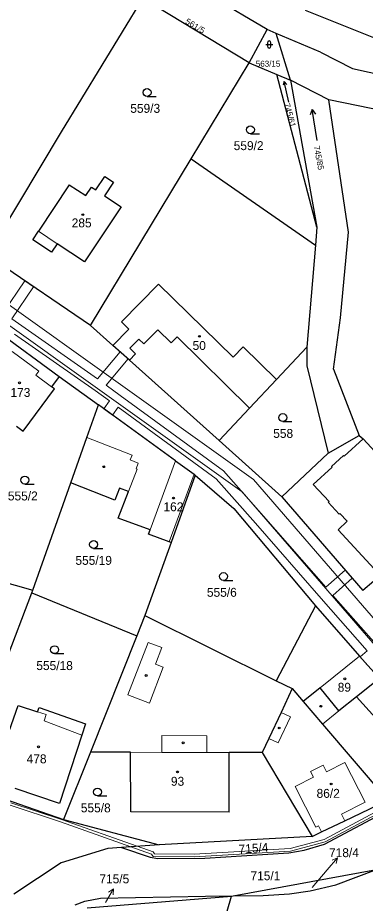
# Model space of a CAD drawing. Extents: x -701211 to -698780, y -1014269 to -1012378.
# Drawn here: x -700367.7 to -700301.5, y -1013402.8 to -1013234 of the extents above; entities that cross this region are included whole.
import ezdxf
from ezdxf.enums import TextEntityAlignment as Align

# ---------------------------------------------------------------- set-up
doc = ezdxf.new("R2010")
doc.units = 0
doc.header["$LTSCALE"] = 0.68
for name, color, linetype, lineweight in [('1', 7, 'Continuous', 25), ('13', 7, 'Continuous', 13), ('3', 7, 'Continuous', 25), ('4', 7, 'Continuous', 13), ('5', 7, 'Continuous', 25), ('7', 7, 'Continuous', 13)]:
    doc.layers.add(name, color=color, linetype=linetype, lineweight=lineweight)
doc.layers.add('2', color=7, linetype='Continuous')

msp = doc.modelspace()

# ---------------------------------------------------------------- linework, layer by layer
at = {"layer": '1'}
for p, q in [((-700320.2, -1013236.27), (-700340.25, -1013224.35)), ((-700359.38, -1013255.74), (-700343.9, -1013230.25)), ((-700323.64, -1013242.58), (-700343.9, -1013230.25)), ((-700312.97, -1013232.56), (-700298.98, -1013238.16)), ((-700323.64, -1013242.58), (-700320.2, -1013236.27)), ((-700318.49, -1013237), (-700320.2, -1013236.27)), ((-700310.08, -1013240.6), (-700318.49, -1013237)), ((-700310.08, -1013240.6), (-700303.94, -1013243.67)), ((-700334.69, -1013260.9), (-700323.64, -1013242.58)), ((-700323.64, -1013242.58), (-700318.37, -1013244.83)), ((-700303.94, -1013243.67), (-700289.22, -1013247.02)), ((-700310.73, -1013273.92), (-700318.37, -1013244.83)), ((-700318.37, -1013244.83), (-700315.79, -1013245.93)), ((-700315.79, -1013245.93), (-700310.73, -1013273.92)), ((-700288.68, -1013253.7), (-700308.46, -1013249.64)), ((-700304.74, -1013274.86), (-700308.46, -1013249.64)), ((-700373.52, -1013279.35), (-700359.38, -1013255.74)), ((-700353.86, -1013292.67), (-700334.69, -1013260.9)), ((-700334.69, -1013260.9), (-700311.02, -1013277.36)), ((-700352.87, -1013266.84), (-700351.16, -1013264.26)), ((-700351.16, -1013264.26), (-700349.49, -1013265.36)), ((-700357.91, -1013265.85), (-700363.78, -1013274.73)), ((-700357.91, -1013265.85), (-700354.78, -1013267.92)), ((-700354.78, -1013267.92), (-700353.71, -1013266.29)), ((-700353.71, -1013266.29), (-700352.87, -1013266.84)), ((-700349.49, -1013265.36), (-700351.2, -1013267.94)), ((-700351.2, -1013267.94), (-700348.01, -1013270.05)), ((-700348.01, -1013270.05), (-700355.04, -1013280.57)), ((-700364.86, -1013276.35), (-700363.78, -1013274.73)), ((-700310.73, -1013273.92), (-700311.02, -1013277.36)), ((-700306.25, -1013291.23), (-700304.74, -1013274.86)), ((-700361.33, -1013278.71), (-700364.86, -1013276.35)), ((-700360.25, -1013277.09), (-700361.33, -1013278.71)), ((-700355.04, -1013280.57), (-700360.25, -1013277.09)), ((-700311.02, -1013277.36), (-700312.68, -1013296.79)), ((-700353.86, -1013292.67), (-700373.52, -1013279.35)), ((-700307.57, -1013300.99), (-700306.25, -1013291.23)), ((-700373.75, -1013292.22), (-700359.82, -1013302.39)), ((-700349.61, -1013296.47), (-700353.86, -1013292.67)), ((-700346.46, -1013299.29), (-700349.61, -1013296.47)), ((-700312.68, -1013296.79), (-700318.45, -1013302.95)), ((-700312.68, -1013296.79), (-700312.67, -1013300.36)), ((-700329.36, -1013314.6), (-700346.46, -1013299.29)), ((-700312.67, -1013300.36), (-700308.61, -1013317.04)), ((-700307.57, -1013300.99), (-700302.67, -1013313.63)), ((-700359.82, -1013302.39), (-700361.27, -1013304.37)), ((-700359.82, -1013302.39), (-700352.35, -1013307.84)), ((-700318.45, -1013302.95), (-700323.58, -1013308.43)), ((-700366.69, -1013312.84), (-700360.75, -1013304.75)), ((-700360.75, -1013304.75), (-700361.27, -1013304.37)), ((-700354.54, -1013314.02), (-700352.35, -1013307.84)), ((-700337.69, -1013318.48), (-700352.35, -1013307.84)), ((-700323.58, -1013308.43), (-700329.36, -1013314.6)), ((-700367.98, -1013311.89), (-700366.69, -1013312.84)), ((-700308.61, -1013317.04), (-700302.67, -1013313.63)), ((-700302.67, -1013313.63), (-700301.95, -1013314.29)), ((-700357.61, -1013322.7), (-700354.54, -1013314.02)), ((-700317.43, -1013325.38), (-700329.36, -1013314.6)), ((-700301.95, -1013314.29), (-700298.93, -1013317.54)), ((-700308.61, -1013317.04), (-700317.43, -1013325.38)), ((-700337.69, -1013318.48), (-700334.15, -1013321.05)), ((-700333.92, -1013321.25), (-700338.52, -1013334.05)), ((-700334.15, -1013321.05), (-700333.92, -1013321.25)), ((-700333.92, -1013321.25), (-700326.57, -1013327.6)), ((-700364.85, -1013343.16), (-700357.61, -1013322.7)), ((-700349.24, -1013325.97), (-700357.61, -1013322.7)), ((-700348.36, -1013323.68), (-700349.24, -1013325.97)), ((-700346.63, -1013324.34), (-700348.36, -1013323.68)), ((-700348.57, -1013329.39), (-700346.63, -1013324.34)), ((-700317.43, -1013325.38), (-700301.97, -1013343.21)), ((-700326.57, -1013327.6), (-700311.03, -1013346.12)), ((-700342.53, -1013331.62), (-700348.57, -1013329.39)), ((-700342.84, -1013332.46), (-700342.53, -1013331.62)), ((-700338.52, -1013334.05), (-700343.52, -1013347.99)), ((-700338.9, -1013333.91), (-700342.84, -1013332.46)), ((-700338.52, -1013334.05), (-700338.9, -1013333.91)), ((-700388.79, -1013336.44), (-700364.85, -1013343.16)), ((-700299.89, -1013341.43), (-700301.97, -1013343.21)), ((-700370.05, -1013356.84), (-700365.02, -1013343.65)), ((-700365.02, -1013343.65), (-700364.85, -1013343.16)), ((-700365.02, -1013343.65), (-700345.07, -1013351.88)), ((-700311.03, -1013346.12), (-700318.51, -1013360.46)), ((-700311.03, -1013346.12), (-700302.61, -1013355.72)), ((-700343.52, -1013347.99), (-700345.07, -1013351.88)), ((-700343.52, -1013347.99), (-700318.51, -1013360.46)), ((-700345.07, -1013351.88), (-700353.89, -1013374.04)), ((-700302.61, -1013355.72), (-700298.84, -1013359.96)), ((-700318.51, -1013360.46), (-700315.45, -1013361.91)), ((-700298.84, -1013359.96), (-700303.19, -1013363.48)), ((-700315.45, -1013361.91), (-700317.57, -1013366.44)), ((-700315.45, -1013361.91), (-700313.33, -1013364.39)), ((-700310.1, -1013361.77), (-700313.33, -1013364.39)), ((-700306.53, -1013366.18), (-700310.1, -1013361.77)), ((-700313.33, -1013364.39), (-700309.65, -1013368.7)), ((-700303.19, -1013363.48), (-700306.53, -1013366.18)), ((-700372.21, -1013378.05), (-700367.64, -1013365.14)), ((-700367.64, -1013365.14), (-700363.99, -1013366.32)), ((-700363.99, -1013366.32), (-700363.67, -1013365.52)), ((-700363.67, -1013365.52), (-700354.85, -1013368.61)), ((-700317.57, -1013366.44), (-700319.9, -1013371.4)), ((-700354.85, -1013368.61), (-700355.55, -1013370.8)), ((-700309.65, -1013368.7), (-700297.27, -1013383.2)), ((-700355.55, -1013370.8), (-700359.78, -1013383.8)), ((-700319.9, -1013371.4), (-700321.18, -1013374.12)), ((-700353.89, -1013374.04), (-700359, -1013386.88)), ((-700346.24, -1013374.05), (-700353.89, -1013374.04)), ((-700346.19, -1013385.41), (-700346.24, -1013374.05)), ((-700327.42, -1013385.46), (-700327.47, -1013374.1)), ((-700321.18, -1013374.12), (-700327.47, -1013374.1)), ((-700321.18, -1013374.12), (-700311.61, -1013390.1)), ((-700378.88, -1013380), (-700359, -1013386.88)), ((-700359.78, -1013383.8), (-700368.23, -1013380.97)), ((-700309.31, -1013391.58), (-700293.7, -1013383.22)), ((-700305.41, -1013387.12), (-700297.27, -1013383.2)), ((-700327.42, -1013385.46), (-700346.19, -1013385.41)), ((-700359, -1013386.88), (-700340.79, -1013391.69)), ((-700309.83, -1013389.24), (-700305.41, -1013387.12)), ((-700311.61, -1013390.1), (-700309.83, -1013389.24)), ((-700311.61, -1013390.1), (-700340.79, -1013391.69)), ((-700350.58, -1013392.37), (-700359.49, -1013395.11)), ((-700347.99, -1013392.19), (-700350.58, -1013392.37)), ((-700340.79, -1013391.69), (-700347.99, -1013392.19)), ((-700347.99, -1013392.19), (-700342.52, -1013394.08)), ((-700316.07, -1013393.23), (-700313.15, -1013392.71)), ((-700313.15, -1013392.71), (-700309.31, -1013391.58)), ((-700342.52, -1013394.08), (-700341.04, -1013394.33)), ((-700341.04, -1013394.33), (-700332.06, -1013394.22)), ((-700332.06, -1013394.22), (-700316.07, -1013393.23)), ((-700359.49, -1013395.11), (-700368.46, -1013401.1)), ((-700326.66, -1013401.42), (-700299.4, -1013396.43)), ((-700307.14, -1013399.33), (-700299.4, -1013396.43)), ((-700311.99, -1013400.47), (-700307.14, -1013399.33)), ((-700354.53, -1013403.68), (-700327.02, -1013401.49)), ((-700351.96, -1013401.87), (-700331.97, -1013401.5)), ((-700331.97, -1013401.5), (-700326.66, -1013401.42)), ((-700328.91, -1013408.1), (-700327.02, -1013401.49)), ((-700327.02, -1013401.49), (-700326.66, -1013401.42)), ((-700326.66, -1013401.42), (-700320.96, -1013401.34)), ((-700320.96, -1013401.34), (-700315.97, -1013401.01)), ((-700315.97, -1013401.01), (-700311.99, -1013400.47)), ((-700356.82, -1013403.15), (-700354.92, -1013402.44)), ((-700354.92, -1013402.44), (-700351.96, -1013401.87))]:
    msp.add_line(p, q, dxfattribs=at)
msp.add_lwpolyline([(-700308.46, -1013249.64), (-700315.79, -1013245.93), (-700318.49, -1013237)], dxfattribs=at)
at = {"layer": '13'}
for points in [[(-700287.36, -1013363.02), (-700322.83, -1013322.02), (-700397.37, -1013268.79), (-700422.31, -1013253.72), (-700469.35, -1013225.78), (-700474.13, -1013223.15), (-700505.21, -1013205.06), (-700510.59, -1013202.27), (-700527.33, -1013194.88), (-700555.49, -1013183.11), (-700559.92, -1013181.38), (-700563.23, -1013179.64), (-700564.89, -1013177.43), (-700602.93, -1013162.92), (-700645.95, -1013152.22), (-700656.81, -1013151.49), (-700669.27, -1013150.25), (-700710.28, -1013153.93)], [(-700710.03, -1013157.08), (-700669.29, -1013153.42), (-700657.08, -1013154.63), (-700646.44, -1013155.36), (-700603.88, -1013165.94), (-700566.87, -1013180.06), (-700565.33, -1013182.09), (-700561.6, -1013184.11), (-700556.67, -1013186.04), (-700528.57, -1013197.79), (-700511.95, -1013205.13), (-700506.73, -1013207.83), (-700475.69, -1013225.9), (-700470.91, -1013228.52), (-700423.94, -1013256.43), (-700399.11, -1013271.43), (-700324.98, -1013324.37), (-700289.83, -1013365.01)], [(-700298.96, -1013354.08), (-700307.69, -1013344.13), (-700303.99, -1013340.88), (-700305.32, -1013339.34), (-700309.03, -1013342.6), (-700320.9, -1013329.04), (-700328.52, -1013320.38), (-700348.23, -1013306), (-700350.86, -1013304.05), (-700346.7, -1013299.07), (-700348.22, -1013297.72), (-700352.51, -1013302.86), (-700368.88, -1013291.43), (-700364.71, -1013285.32), (-700366.39, -1013284.18), (-700370.54, -1013290.25)], [(-700368.32, -1013294.34), (-700352.95, -1013305.07), (-700350.27, -1013307.06), (-700351.35, -1013308.56), (-700349.71, -1013309.76), (-700348.63, -1013308.27), (-700329.92, -1013321.91)], [(-700329.92, -1013321.91), (-700322.45, -1013330.4), (-700309.92, -1013344.72), (-700301.18, -1013354.69), (-700302.5, -1013355.85), (-700301.15, -1013357.37)], [(-700369.19, -1013384.15), (-700359.56, -1013387.33), (-700346.2, -1013392.07), (-700344.95, -1013391.98), (-700359.4, -1013386.85), (-700369.07, -1013383.67)], [(-700298.83, -1013385.05), (-700309.37, -1013390.68), (-700315.82, -1013392.4), (-700334.11, -1013393.48), (-700341.66, -1013393.41), (-700341.96, -1013393.04), (-700344.95, -1013391.98), (-700346.2, -1013392.07), (-700342.26, -1013393.46), (-700341.9, -1013393.91), (-700334.09, -1013393.98), (-700315.74, -1013392.9), (-700309.19, -1013391.14), (-700298.59, -1013385.49)]]:
    msp.add_lwpolyline(points, dxfattribs=at)
at = {"layer": '3'}
for p, q in [((-700320.491, -1013239.111), (-700319.149, -1013239.111)), ((-700320.155, -1013238.775), (-700320.155, -1013239.446)), ((-700319.485, -1013239.446), (-700319.485, -1013238.775)), ((-700316.945, -1013246.161), (-700316.48, -1013246.732)), ((-700343.093, -1013249.01), (-700341.343, -1013249.01)), ((-700311.654, -1013251.479), (-700311.005, -1013252.365)), ((-700323.403, -1013256.12), (-700321.653, -1013256.12)), ((-700317.233, -1013310.99), (-700315.483, -1013310.99)), ((-700366.383, -1013322.91), (-700364.633, -1013322.91)), ((-700353.283, -1013335.19), (-700351.533, -1013335.19)), ((-700328.533, -1013341.28), (-700326.783, -1013341.28)), ((-700360.713, -1013355.25), (-700358.963, -1013355.25)), ((-700352.533, -1013382.38), (-700350.783, -1013382.38))]:
    msp.add_line(p, q, dxfattribs=at)
for points in [[(-700316.109, -1013250.094), (-700316.945, -1013246.161), (-700317.137, -1013246.872)], [(-700310.715, -1013257.405), (-700311.654, -1013251.479), (-700311.996, -1013252.522)]]:
    msp.add_lwpolyline(points, dxfattribs=at)
for centre in [(-700343.0929, -1013248.2598), (-700323.4029, -1013255.3698), (-700317.2329, -1013310.2398), (-700366.3829, -1013322.1598), (-700353.2829, -1013334.4398), (-700328.5329, -1013340.5298), (-700360.7129, -1013354.4998), (-700352.5329, -1013381.6298)]:
    msp.add_circle(centre, 0.75, dxfattribs=at)
for centre, start, end in [((-700319.82, -1013238.7756), 0, 180), ((-700319.82, -1013239.4456), 180, 359.98789)]:
    msp.add_arc(centre, 0.335, start, end, dxfattribs=at)
at = {"layer": '4'}
for p, q in [((-700363.78, -1013274.73), (-700360.25, -1013277.09)), ((-700347.99, -1013291.97), (-700340.9, -1013284.78)), ((-700326.72, -1013298.74), (-700340.9, -1013284.78)), ((-700349.61, -1013296.47), (-700346.56, -1013293.38)), ((-700347.99, -1013291.97), (-700346.56, -1013293.38)), ((-700343.72, -1013296.17), (-700341.07, -1013293.48)), ((-700341.07, -1013293.48), (-700338.5, -1013296)), ((-700338.5, -1013296), (-700337.36, -1013294.86)), ((-700323.58, -1013308.43), (-700337.36, -1013294.86)), ((-700346.38, -1013297.03), (-700344.64, -1013295.27)), ((-700343.72, -1013296.17), (-700344.64, -1013295.27)), ((-700326.72, -1013298.74), (-700324.76, -1013296.74)), ((-700324.76, -1013296.74), (-700318.45, -1013302.95)), ((-700363.69, -1013301.41), (-700368.8, -1013297.64)), ((-700345.29, -1013298.1), (-700346.46, -1013299.29)), ((-700346.38, -1013297.03), (-700345.29, -1013298.1)), ((-700305.55, -1013317.57), (-700301.95, -1013314.29)), ((-700346.3, -1013318.31), (-700344.76, -1013318.91)), ((-700337.69, -1013318.48), (-700342.53, -1013331.62)), ((-700307.95, -1013319.55), (-700305.69, -1013317.45)), ((-700305.69, -1013317.45), (-700305.55, -1013317.57)), ((-700346.63, -1013324.34), (-700345, -1013320.09)), ((-700345.19, -1013320.02), (-700344.76, -1013318.91)), ((-700345, -1013320.09), (-700345.19, -1013320.02)), ((-700311.43, -1013322.97), (-700307.83, -1013319.67)), ((-700307.83, -1013319.67), (-700307.95, -1013319.55)), ((-700334.15, -1013321.05), (-700338.9, -1013333.91)), ((-700308.43, -1013326.21), (-700311.43, -1013322.97)), ((-700308.57, -1013326.35), (-700308.43, -1013326.21)), ((-700306.47, -1013328.63), (-700308.57, -1013326.35)), ((-700306.38, -1013328.52), (-700306.47, -1013328.63)), ((-700304.98, -1013330.02), (-700306.38, -1013328.52)), ((-700306.69, -1013331.65), (-700304.98, -1013330.02)), ((-700299.83, -1013339.08), (-700306.69, -1013331.65)), ((-700346.78, -1013363.1), (-700342.91, -1013353.09)), ((-700342.91, -1013353.09), (-700340.29, -1013354.1)), ((-700341.51, -1013357.25), (-700340.29, -1013354.1)), ((-700310.1, -1013361.77), (-700302.61, -1013355.72)), ((-700341.51, -1013357.25), (-700340, -1013357.83)), ((-700342.65, -1013364.69), (-700340, -1013357.83)), ((-700342.65, -1013364.69), (-700346.78, -1013363.1)), ((-700288.98, -1013379.34), (-700303.19, -1013363.48)), ((-700317.57, -1013366.44), (-700315.76, -1013367.29)), ((-700306.53, -1013366.18), (-700309.65, -1013368.7)), ((-700355.55, -1013370.8), (-700362.7, -1013368.07)), ((-700340.27, -1013374.07), (-700340.28, -1013370.87)), ((-700340.28, -1013370.87), (-700331.73, -1013370.89)), ((-700331.71, -1013374.09), (-700331.73, -1013370.89)), ((-700346.24, -1013374.05), (-700340.27, -1013374.07)), ((-700340.27, -1013374.07), (-700331.71, -1013374.09)), ((-700331.71, -1013374.09), (-700327.47, -1013374.1)), ((-700308.9, -1013377.75), (-700305.42, -1013375.99)), ((-700301.57, -1013383.57), (-700305.42, -1013375.99)), ((-700311.94, -1013377.73), (-700309.53, -1013376.51)), ((-700311.4, -1013378.8), (-700311.94, -1013377.73)), ((-700308.9, -1013377.75), (-700309.53, -1013376.51)), ((-700314.87, -1013380.56), (-700311.4, -1013378.8)), ((-700310.93, -1013388.33), (-700314.87, -1013380.56)), ((-700306.03, -1013385.83), (-700301.57, -1013383.57)), ((-700305.41, -1013387.12), (-700306.03, -1013385.83)), ((-700310.4, -1013388.05), (-700310.93, -1013388.33)), ((-700310.4, -1013388.05), (-700309.83, -1013389.24))]:
    msp.add_line(p, q, dxfattribs=at)
for points in [[(-700361.27, -1013304.37), (-700364.26, -1013302.18), (-700363.69, -1013301.41)], [(-700346.3, -1013318.31), (-700345.94, -1013317.38), (-700354.54, -1013314.02)], [(-700362.7, -1013368.07), (-700362.32, -1013366.87), (-700363.99, -1013366.32)], [(-700319.9, -1013371.4), (-700318.09, -1013372.25), (-700315.76, -1013367.29)]]:
    msp.add_lwpolyline(points, dxfattribs=at)
at = {"layer": '5'}
for centre in [(-700355.3368, -1013271.5492), (-700333.1268, -1013294.7492), (-700367.3868, -1013303.6192), (-700351.3468, -1013319.6092), (-700338.0668, -1013325.5792), (-700343.2668, -1013359.4192), (-700305.4268, -1013360.0392), (-700309.9968, -1013365.2792), (-700317.9068, -1013369.4192), (-700363.7868, -1013373.0192), (-700336.2268, -1013372.2392), (-700337.2868, -1013377.7992), (-700308.0168, -1013380.0992)]:
    msp.add_circle(centre, 0.175, dxfattribs=at)
at = {"layer": '7'}
for p, q in [((-700306.781, -1013394.195), (-700307.816, -1013394.622)), ((-700349.474, -1013400.108), (-700350.419, -1013400.708))]:
    msp.add_line(p, q, dxfattribs=at)
for points in [[(-700311.64, -1013399.84), (-700308.75, -1013396.46), (-700306.781, -1013394.195), (-700307.06, -1013395.279)], [(-700351.02, -1013402.68), (-700349.474, -1013400.108), (-700349.561, -1013401.224)]]:
    msp.add_lwpolyline(points, dxfattribs=at)

# ---------------------------------------------------------------- texts
at = {"layer": '2', "width": 1.05}
msp.add_text('561/5', height=1.14, rotation=329, dxfattribs=at).set_placement((-700334.2166, -1013236.0532), align=Align.CENTER)
at = {"layer": '2'}
for s, height, p in [('563/15', 1.14, (-700320.039, -1013243.345)), ('478', 1.7, (-700364.139, -1013376.155)), ('718/4', 1.7, (-700305.58, -1013394.045)), ('715/5', 1.7, (-700349.33, -1013399.035))]:
    msp.add_text(s, height=height, dxfattribs=at).set_placement(p, align=Align.CENTER)
for s, p in [('559/3', (-700346.29, -1013252.135)), ('559/2', (-700326.59, -1013259.245)), ('285', (-700357.45, -1013273.975)), ('50', (-700334.42, -1013297.345)), ('173', (-700369.12, -1013306.295)), ('558', (-700319.06, -1013314.115)), ('555/2', (-700369.61, -1013326.035)), ('162', (-700339.97, -1013328.095)), ('555/19', (-700356.74, -1013338.315)), ('555/6', (-700331.69, -1013344.405)), ('555/18', (-700364.19, -1013358.375)), ('89', (-700306.77, -1013362.505)), ('93', (-700338.55, -1013380.435)), ('86/2', (-700310.8, -1013382.735)), ('555/8', (-700355.71, -1013385.505)), ('715/1', (-700323.39, -1013398.445))]:
    msp.add_text(s, height=1.7, dxfattribs=at).set_placement(p)
for s, height, rotation, p in [('745/61', 1.14, 285, (-700316.4142, -1013252.7285)), ('745/85', 1.14, 281, (-700310.9287, -1013260.8192)), ('715/4', 1.7, 4, (-700322.7593, -1013393.201))]:
    msp.add_text(s, height=height, rotation=rotation, dxfattribs=at).set_placement(p, align=Align.CENTER)

doc.saveas('drawing.dxf')
